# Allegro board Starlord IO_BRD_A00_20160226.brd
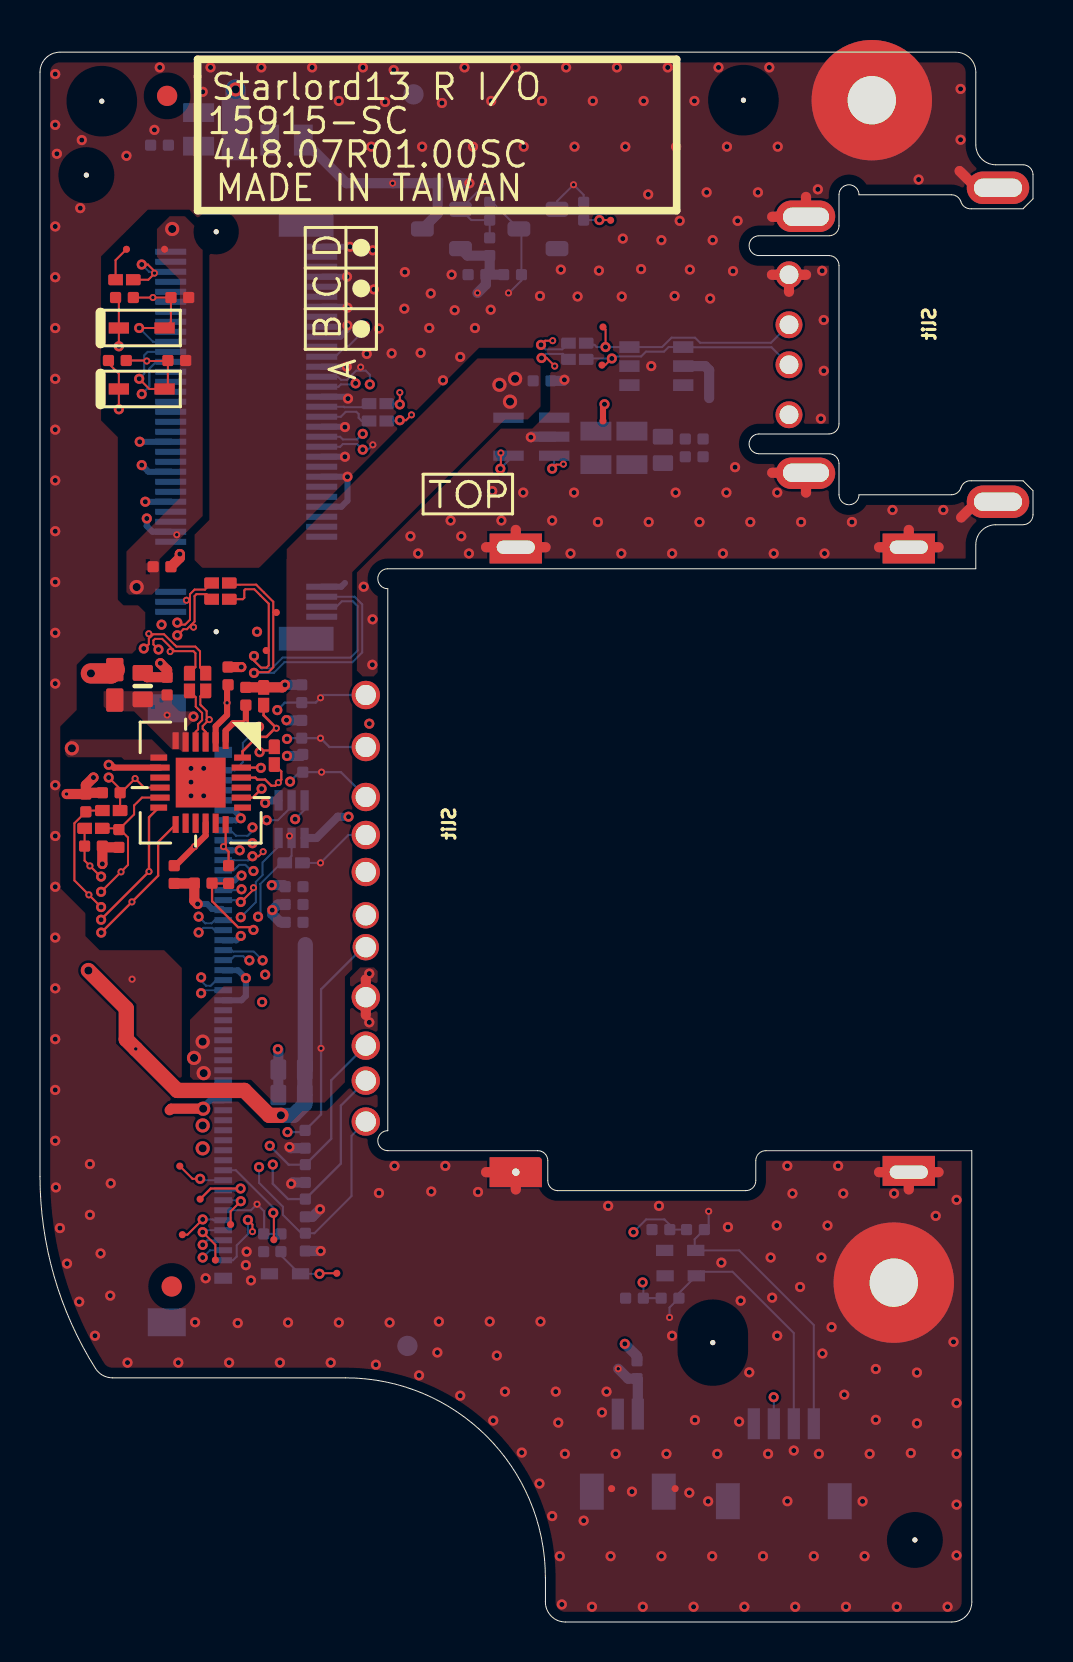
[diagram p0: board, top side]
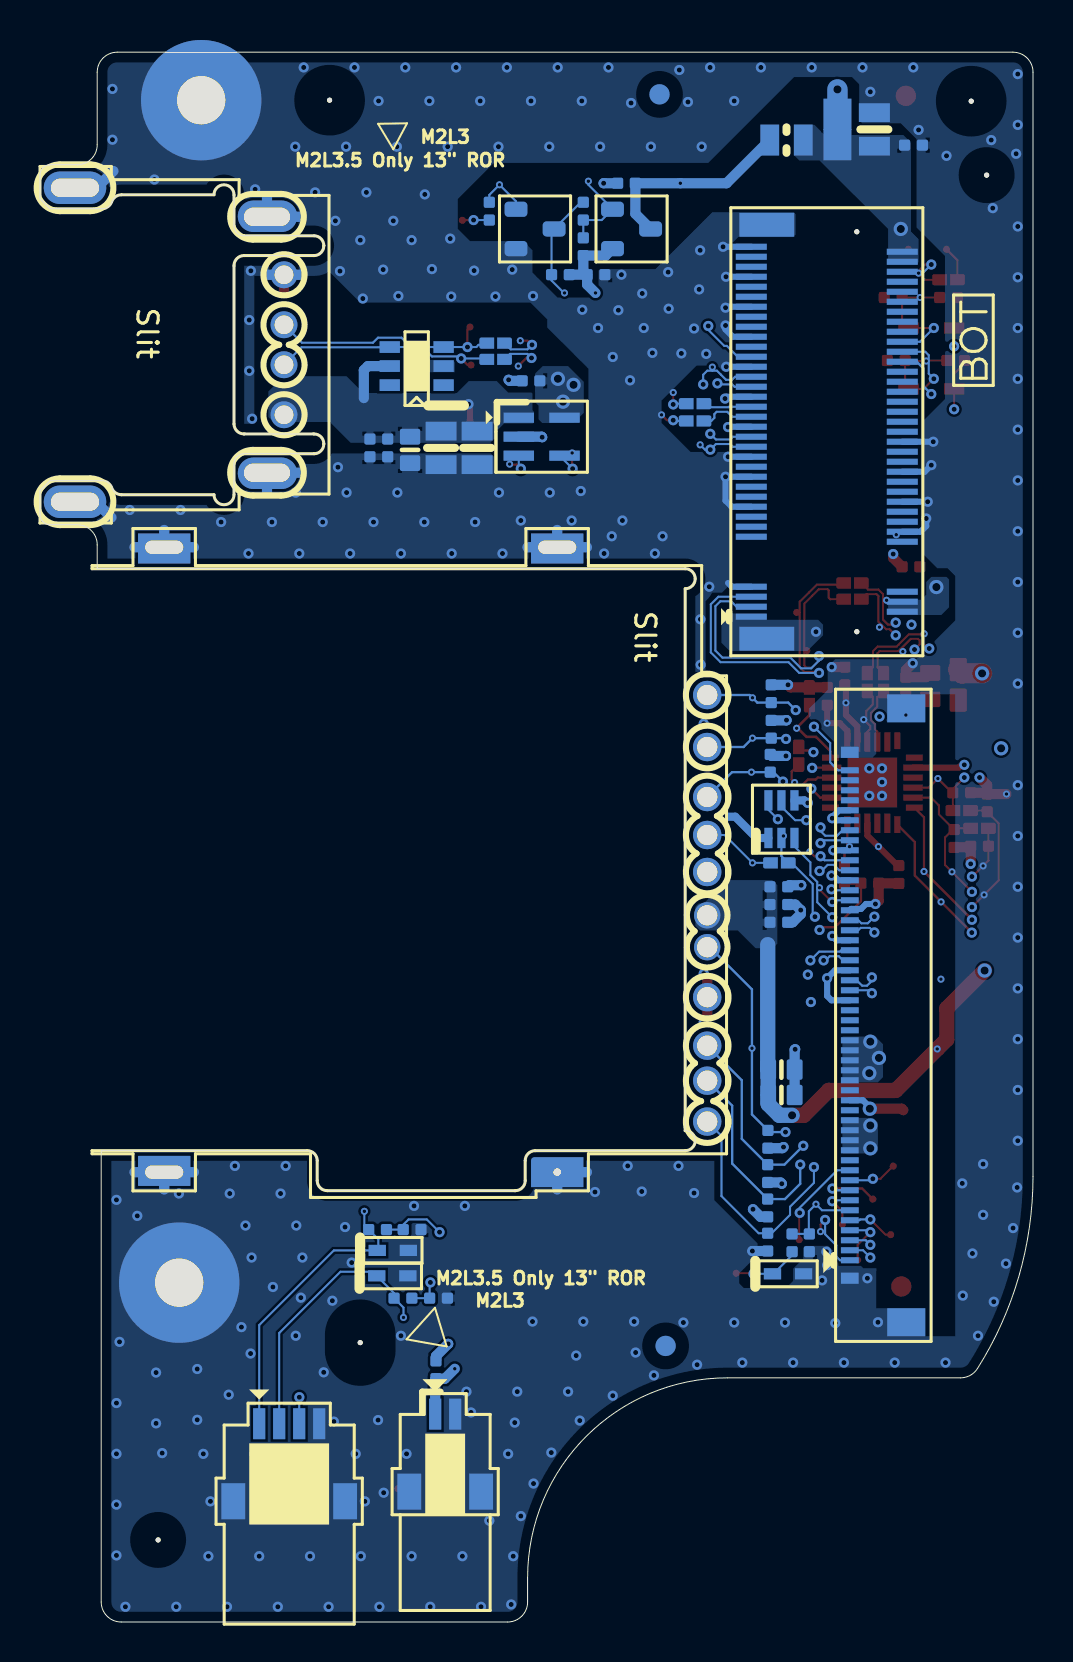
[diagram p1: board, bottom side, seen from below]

Outline 49.65 x 78.5 mm; copper layers: TOP, L2GND, L3, L4, L5VCC, L6, L7GND, BOTTOM. Coordinates in mm from the lower left corner of the outline.
Outline path: 0,77.5 0,22.28 arc(0.71,17.28) 2.78,12.68 arc(3.14,12.33) 3.62,12.21 15.27,12.21 arc(22.34,9.28) 25.27,2.21 25.27,1 arc(25.56,0.29) 26.27,0 45.59,0 arc(46.3,0.29) 46.59,1 46.59,23.57 36.29,23.57 arc(35.94,23.42) 35.79,23.07 35.79,22.07 arc(35.64,21.72) 35.29,21.57 25.89,21.57 arc(25.54,21.72) 25.39,22.07 25.39,23.07 arc(25.24,23.42) 24.89,23.57 17.39,23.57 arc(16.89,24.07) 17.39,24.57 17.39,51.67 arc(16.89,52.17) 17.39,52.67 46.79,52.67 46.79,53.87 arc(47.08,54.58) 47.79,54.87 49.15,54.87 arc(49.5,55.02) 49.65,55.37 49.65,56.57 49.15,57.07 46.57,57.07 arc(46.25,56.99) 46.05,56.72 arc(45.87,56.47) 45.57,56.37 40.95,56.37 arc(40.45,55.87) 39.95,56.37 39.95,57.92 arc(39.8,58.27) 39.45,58.42 35.95,58.42 arc(35.46,58.92) 35.95,59.41 39.45,59.41 arc(39.8,59.56) 39.95,59.91 39.95,67.83 arc(39.8,68.18) 39.45,68.33 35.95,68.33 arc(35.46,68.83) 35.95,69.32 39.45,69.32 arc(39.8,69.47) 39.95,69.82 39.95,71.37 arc(40.45,71.87) 40.95,71.37 45.57,71.37 arc(45.87,71.27) 46.05,71.02 arc(46.25,70.75) 46.57,70.67 49.15,70.67 49.65,71.17 49.65,72.37 arc(49.5,72.72) 49.15,72.87 47.79,72.87 arc(47.08,73.16) 46.79,73.87 46.79,77.5 arc(46.5,78.21) 45.79,78.5 1,78.5 arc(0.29,78.21) 0,77.5

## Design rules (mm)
constraint set DEFAULT: min track width 0.127, pair gap 0.102
net group POWER_20: nets +RTC_VCC RTC_VCC_C
net group POWER_60: nets 3D3V_S5 WLANPWR
net group CARD_CLK: nets 12MHZ_IN
net group CPU_SIDE: nets PLT_RST#
net group OTHER_4: nets AUX_EN_WOWL AUX_EN_WOWL_R BLUETOOTH_EN BLUETOOTH_EN_R CLKREQ_PCIE#1 JIO3_PCIE_WAKE# JIO3_PCIE_WAKE#_R KBC_PWRBTN# KBC_PWRBTN#_C LOOP SD_CD# SD_CD#_C SD_CD#_CARD SD_WP#/MS_DATA1 SD_WP#/MS_DATA1_C USB_OC1# USB_PWR_EN# VOL_DOWN# VOL_DOWN#_R VOL_UP# VOL_UP#_R WIFI_RF_EN WIFI_RF_EN_R WLAN_EN# WLAN_EN_R#
net group POWER_12: nets CARD_AV18 CARD_RREF SDREG
net group SD_MMC_SIG-MWS: nets SD_MMC_CLK/MS_DATA2 SD_MMC_CMM/MS_DATA3 SD_MMC_DAT1 SD_MMC_DATA0/MS_DATA5 SD_MMC_DATA2/MS_BS SD_MMC_DATA3/MS_CLK SD_MMC_DATA3/MS_CLK_R SP5

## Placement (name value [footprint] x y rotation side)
AFTP710  AFTE14P-GP  [AFTE14P-75]  31.76 6.67 0 top
AFTP716  AFTE14P-GP  [AFTE14P-75]  14.84 17.44 0 top
AFTP717  AFTE14P-GP  [AFTE14P-75]  11.69 19.12 0 top
AFTP718  AFTE14P-GP  [AFTE14P-75]  6.99 22.8 0 top
AFTP2507  AFTE14P-GP  [AFTE14P-75]  28.58 6.67 0 top
AFTP2508  AFTE14P-GP  [AFTE14P-75]  6.48 25.59 0 top
AFTP3404  DO NOT STUFF  [AFTE14P-75]  28.1 62.85 0 top
AFTP3405  DO NOT STUFF  [AFTE14P-75]  28.15 64.76 0 top
AFTP3406  DO NOT STUFF  [AFTE14P-75]  28.15 60.06 0 top
AFTP6108  DO NOT STUFF  [AFTE14P-75]  8.01 21.15 0 top
AFTP6109  DO NOT STUFF  [AFTE14P-75]  9.53 19.88 0 top
AFTP6110  DO NOT STUFF  [AFTE14P-75]  7.12 19.37 0 top
AFTP6111  DO NOT STUFF  [AFTE14P-75]  11.82 50.48 0 top
AFTP6112  DO NOT STUFF  [AFTE14P-75]  8.77 18.1 0 top
AFTP6113  DO NOT STUFF  [AFTE14P-75]  6.23 68.65 0 top
AFTP6114  DO NOT STUFF  [AFTE14P-75]  11.31 48.58 0 top
AFTP6115  DO NOT STUFF  [AFTE14P-75]  4.32 68.65 0 top
AFTP6117  DO NOT STUFF  [AFTE14P-75]  28.53 70.09 0 top
C311  SCD1U10V2KX-5GP  [C402H22]  12.71 35.88 90 bottom
C312  SCD01U16V2KX-3GP  [C402H22]  12.71 36.77 90 bottom
C313  SC4D7U6D3V3KX-GP  [C603H36]  12.58 27.62 90 bottom
C314  SC10U6D3V3KX-GP  [C603H38]  12.58 26.35 90 bottom
C315  DO NOT STUFF  [C402H22]  8.16 36.95 270 top
C316  SCD1U10V2KX-5GP  [C402H22]  6.36 46.8 180 top
C317  SC4D7U6D3V3KX-GP  [C603H36]  5.14 46.8 180 top
C318  SC1U6D3V2KX-GP  [C402H22]  10.29 46.29 180 top
C319  SC1U6D3V2KX-GP  [C402H22]  6.71 37.38 0 top
C320  SCD1U10V2KX-5GP  [C402H22]  12.71 34.99 90 bottom
C413  SC22U6D3V5MX-2GP  [C805H58]  27.79 58.71 180 bottom
C414  SC22U6D3V5MX-2GP  [C805H58]  29.6 58.71 180 bottom
C429  SCD1U16V2KX-3GP  [C402H22]  25.1 62.07 270 bottom
C431  SCD1U16V2KX-3GP  [C402H22]  33.15 58.71 180 bottom
C432  SC1U25V3KX-1-GP  [C603H36]  31.15 58.61 180 bottom
C507  DO NOT STUFF  [C402H22]  22.49 68.77 0 bottom
C508  DO NOT STUFF  [C402H22]  20.33 71.95 270 bottom
C509  DO NOT STUFF  [C402H22]  21.85 67.38 90 bottom
C510  SCD1U16V2KX-3GP  [C402H22]  5.98 73.85 90 bottom
C511  SCD1U16V2KX-3GP  [C402H22]  6.1 52.77 90 top
C512  SC10U6D3V5KX-1GP  [C805H54]  7.93 74.64 0 bottom
CARD34  RTS5176E-GRT-GP  [QFN24-G2D5H40-U]  8.03 41.98 0 top
D503  RB751V-40H-GP  [SOD323AKH38]  5.09 61.66 270 top
D504  RB751V-40H-GP  [SOD323AKH38]  5.09 64.71 270 top
EC308  SC6D8P50V2DN-GP  [C402H22]  13.27 22.42 180 bottom
EC309  SC6D8P50V2DN-GP  [C402H22]  13.27 19 180 bottom
EC310  SC6D8P50V2DN-GP  [C402H22]  13.27 20.71 180 bottom
EC311  SC6D8P50V2DN-GP  [C402H22]  13.25 24.14 180 bottom
EC312  SC6D8P50V2DN-GP  [C402H22]  13.09 46.42 0 bottom
EC313  SC6D8P50V2DN-GP  [C402H22]  13.14 42.94 0 bottom
EC314  SC6D8P50V2DN-GP  [C402H22]  13.09 44.64 0 bottom
EC609  SC1KP50V2KX-1GP  [C402H22]  31.04 19.62 270 bottom
EC610  SC1KP50V2KX-1GP  [C402H22]  29.72 16.19 270 bottom
EC611  SCD1U25V2KX-GP  [C402H22]  11.18 18.96 180 bottom
ED609  AZ5125-01H-R7G-GP  [SOD-523-4H28]  12.25 17.41 90 bottom
ED610  AZ5125-01H-R7G-GP  [SOD-523-4H28]  32.04 17.31 90 bottom
ED611  AZ5125-01H-R7G-GP  [SOD-523-4H28]  32.01 18.58 90 bottom
H11  HOLE237R95-GP  [HOLE237R95]  41.59 76.1 180 bottom
H12  HOLE237R95-GP  [HOLE237R95]  42.69 16.97 180 bottom
IOBD2  IPEX-CON50-1-GP  [20455-050E-76]  6.34 30.34 90 bottom
NOREF  -  [unnamed]  3.09 76.05 0 top
NOREF#2  -  [#2]  14.53 67.45 90 top
NOREF#3  -  [#2]  30.03 76.44 0 top
NOREF#4  -  [unnamed]  35.17 76.1 0 top
NOREF#5  *  [unnamed]  6.58 16.78 0 top
NOREF#6  -  [unnamed]  33.64 13.97 0 top
NOREF#7  -  [#2]  -117.09 -19.11 0 top
NOREF#8  -  [unnamed]  43.74 4.1 0 top
NOREF#9  -  [unnamed]  2.32 72.35 0 top
NOREF#10  *  [unnamed]  6.36 76.32 0 top
NOREF#11  -  [#2]  -115.31 -42.48 0 top
NOREF#12  *  [unnamed]  18.37 13.81 180 bottom
NOREF#13  -  [#2]  2.98 64.1 90 bottom
NOREF#14  *  [unnamed]  18.68 76.39 180 bottom
PWBD1  ACES-CON4-29-GP  [50224-0040N-001]  37.19 6.04 180 bottom
Q503  DO NOT STUFF  [SOT23DGS2D4H48]  20.07 69.66 270 bottom
Q504  DO NOT STUFF  [SOT23DGS2D4H44]  24.9 69.66 270 bottom
Q3302  2N7002KDW-GP  [SOT-363H44]  12.58 40.15 180 bottom
R313  10KR2J-3-GP  [R402H16]  3.56 41.47 90 top
R314  -  [0R0402-PAD]  2.67 39.69 270 top
R316  100KR2J-1-GP  [R402H16]  2.67 38.8 270 top
R317  10KR2J-3-GP  [R402H16]  3.94 39.18 180 top
R318  100KR2J-1-GP  [R402H16]  2.29 40.96 0 top
R319  -  [0R0402-PAD]  8.29 47 0 top
R320  -  [0R0402-PAD]  7.47 47 0 top
R321  -  [0R0402-PAD]  12.68 37.96 270 bottom
R322  -  [0R0603-PAD]  3.74 46.78 0 top
R323  -  [0R0402-PAD]  11.18 46.29 180 top
R324  33R2J-2-GP  [R402H16]  9.43 37.38 180 top
R325  -  [0R0402-PAD]  11.72 43.32 0 top
R326  6K2R2F-GP  [R402H16]  9.4 47.31 180 top
R422  DO NOT STUFF  [R402H16]  32.26 58.71 180 bottom
R501  10KR2J-3-GP  [R402H16]  6.99 66.23 270 top
R502  10KR2J-3-GP  [R402H16]  6.84 63.08 270 top
R510  -  [0R0402-PAD]  9.02 51.96 270 top
R511  -  [0R0402-PAD]  9.02 51.14 270 top
R512  -  [0R0805-PAD]  9.78 74.64 180 bottom
R514  DO NOT STUFF  [R805H24]  12.33 74.11 90 bottom
R516  DO NOT STUFF  [R402H16]  27.18 70.55 0 bottom
R517  DO NOT STUFF  [R402H16]  22.49 70.55 180 bottom
R519  DO NOT STUFF  [R402H16]  23.63 67.38 270 bottom
R520  0R2J-2-GP  [R402H16]  4.22 66.23 270 top
R521  0R2J-2-GP  [R402H16]  3.87 63.08 270 top
R522  -  [0R0402-PAD]  16.9 60.92 270 bottom
R523  -  [0R0402-PAD]  16.9 60.06 270 bottom
R524  -  [0R0402-PAD]  4.22 67.12 90 top
R601  1KR2J-1-GP  [R402H16]  29.85 12.61 180 bottom
R613  470R2J-2-GP  [R402H16]  12.05 18.96 180 bottom
R614  470R2J-2-GP  [R402H16]  32.77 19.62 270 bottom
R615  470R2J-2-GP  [R402H16]  31.5 16.19 270 bottom
R3314  -  [0R0402-PAD]  3.56 40.58 270 top
R4032  -  [0R0402-PAD]  26.87 63.95 270 bottom
R4033  -  [0R0402-PAD]  26.87 63.14 270 bottom
RTC1  ACES-CON2-20-GP-U  [50224-0020N-W02]  29.39 6.52 180 bottom
SD1  SDCARD-11P-17-GP  [PSDBR3-11GLBS1NN4H0]  43.44 38.12 270 bottom
U401  SY6288DAAC-GP  [SOT-23-5H56]  24.57 59.27 270 bottom
U402  AZC099-04S-1-GP  [SOT-6H58]  30.82 62.8 90 bottom
USB4  SKT-USB8-186-GP  [SKT-USB8-166140-2]  47.9 63.87 270 bottom
WLAN1  SKT-NGFF75P-64-GP  [DAN05-67306-050001]  8.81 59.52 270 bottom

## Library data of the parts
AFTP710 AFTP716-AFTP718 AFTP2507 AFTP2508 = AFTE14P-75: tolerance: ZZ.AFT14.101
AFTP3404-AFTP3406 AFTP6108-AFTP6115 AFTP6117 = AFTE14P-75
C311 C316 C320 = C402H22: tolerance: 78.10423.2FL
C312 = C402H22: tolerance: 78.10321.2FL
C313 C317 = C603H36: tolerance: 78.47520.5BL
C314 = C603H38: tolerance: 78.10620.5BL
C315 C507-C509 = C402H22
C318 C319 = C402H22: tolerance: 78.10520.5FL
C413 C414 = C805H58: tolerance: 78.22610.51L
C429 C431 C510 C511 = C402H22: tolerance: 78.10421.2FL
C432 = C603H36: tolerance: 78.10522.5BL
C512 = C805H54: tolerance: 78.10620.51L
CARD34 = QFN24-G2D5H40-U: tolerance: 71.05176.A03
D503 D504 = SOD323AKH38: tolerance: 83.R2004.G8F
EC308-EC314 = C402H22: tolerance: 78.6R864.1FL
EC609 EC610 = C402H22: tolerance: 78.10224.2FL
EC611 = C402H22: tolerance: 78.10422.5FL
ED609-ED611 = SOD-523-4H28: tolerance: 75.05125.070
H11 H12 = HOLE237R95: tolerance: ZZ.00PAD.921
IOBD2 = 20455-050E-76: tolerance: 020.F0574.0050
PWBD1 = 50224-0040N-001: tolerance: 20.F1639.004
Q503 = SOT23DGS2D4H48
Q504 = SOT23DGS2D4H44
Q3302 = SOT-363H44: tolerance: 84.2N702.A3F
R313 R317 R501 R502 = R402H16: tolerance: 63.10334.1DL
R314 R319-R321 R323 R325 R510 R511 R522-R524 R3314 R4032 R4033 = 0R0402-PAD: tolerance: ZZ.R0402.ZZZ
R316 R318 = R402H16: tolerance: 63.10434.1DL
R322 = 0R0603-PAD: tolerance: ZZ.R0603.ZZZ
R324 = R402H16: tolerance: 63.33034.1DL
R326 = R402H16: tolerance: 64.62015.6DL
R422 R516 R517 R519 = R402H16
R512 = 0R0805-PAD: tolerance: ZZ.R0805.ZZZ
R514 = R805H24
R520 R521 = R402H16: tolerance: 63.R0034.1DL
R601 = R402H16: tolerance: 63.10234.1DL
R613-R615 = R402H16: tolerance: 63.47134.1DL
RTC1 = 50224-0020N-W02: tolerance: 20.F1639.002
SD1 = PSDBR3-11GLBS1NN4H0: tolerance: 062.10002.0301
U401 = SOT-23-5H56: tolerance: 074.06288.009B
U402 = SOT-6H58: tolerance: 75.09904.07C
USB4 = SKT-USB8-166140-2: tolerance: 022.10005.0861
WLAN1 = DAN05-67306-050001: tolerance: 062.10003.0251

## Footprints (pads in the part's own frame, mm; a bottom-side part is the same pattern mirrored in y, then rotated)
0R0402-PAD
  custom 0.14x0.14 smd: 1(0,0.445) 2(0,-0.445)
0R0603-PAD
  custom 0.216x0.216 smd: 1(0,0.851) 2(0,-0.673)
0R0805-PAD
  rect 1.397x1.562 smd: 1(0,0.965)
  rect 1.397x1.569 smd: 2(0,-0.965)
20455-050E-76
  rect 0.305x0.889 smd: 1(-12.25,2.82) 2(-11.75,2.82) 3(-11.25,2.82) 4(-10.75,2.82) 5(-10.25,2.82) 6(-9.75,2.82) 7(-9.25,2.82) 8(-8.75,2.82) 9(-8.25,2.82) 10(-7.75,2.82) 11(-7.25,2.82) 12(-6.75,2.82) 13(-6.25,2.82) 14(-5.75,2.82) 15(-5.25,2.82) 16(-4.75,2.82) 17(-4.25,2.82) 18(-3.75,2.82) 19(-3.25,2.82) 20(-2.75,2.82) 21(-2.25,2.82) 22(-1.75,2.82) 23(-1.25,2.82) 24(-0.75,2.82) 25(-0.25,2.82) 26(0.25,2.82) 27(0.75,2.82) 28(1.25,2.82) 29(1.75,2.82) 30(2.25,2.82) 31(2.75,2.82) 32(3.25,2.82) 33(3.75,2.82) 34(4.25,2.82) 35(4.75,2.82) 36(5.25,2.82) 37(5.75,2.82) 38(6.25,2.82) 39(6.75,2.82) 40(7.25,2.82) 41(7.75,2.82) 42(8.25,2.82) 43(8.75,2.82) 44(9.25,2.82) 45(9.75,2.82) 46(10.25,2.82) 47(10.75,2.82) 48(11.25,2.82) 49(11.75,2.82) 50(12.25,2.82)
  rect 1.397x1.905 smd: 51(-15.35,0) 52(15.35,0)
  rect 0.559x0.889 smd: 53(-13.15,2.82) 54(13.15,2.82)
50224-0020N-W02
  rect 0.61x1.549 smd: 1(-0.5,3.876) 2(0.5,3.876)
  rect 1.194x1.803 smd: 3(-1.797,0) 4(1.797,0)
50224-0040N-001
  rect 0.61x1.549 smd: 1(-1.5,3.875) 2(-0.5,3.875) 3(0.5,3.875) 4(1.5,3.875)
  rect 1.194x1.803 smd: 5(-2.797,0) 6(2.797,0)
AFTE14P-75
  round 0.356 smd: 1(0,0)
C402H22
  custom 0.14x0.14 smd: 1(0,0.445) 2(0,-0.445)
C603H36
  custom 0.197x0.197 smd: 1(0,0.66) 2(0,-0.66)
C603H38
  custom 0.197x0.197 smd: 1(0,0.66) 2(0,-0.66)
C805H54
  rect 1.549x0.94 smd: 1(0,0.838) 2(0,-0.838)
C805H58
  rect 1.549x0.94 smd: 1(0,0.838) 2(0,-0.838)
DAN05-67306-050001
  round 0.254 hole 1.651 unplated: (-10,0)
  round 0.254 hole 1.168 unplated: (10,0)
  rect 0.305x1.549 smd: 1(9.25,-5.275) 2(9,2.275) 3(8.75,-5.275) 4(8.5,2.275) 5(8.25,-5.275) 6(8,2.275) 7(7.75,-5.275) 16(5.5,2.275) 17(5.25,-5.275) 18(5,2.275) 19(4.75,-5.275) 20(4.5,2.275) 21(4.25,-5.275) 22(4,2.275) 23(3.75,-5.275) 24(3.5,2.275) 25(3.25,-5.275) 26(3,2.275) 27(2.75,-5.275) 28(2.5,2.275) 29(2.25,-5.275) 30(2,2.275) 31(1.75,-5.275) 32(1.5,2.275) 33(1.25,-5.275) 34(1,2.275) 35(0.75,-5.275) 36(0.5,2.275) 37(0.25,-5.275) 38(0,2.275) 39(-0.25,-5.275) 40(-0.5,2.275) 41(-0.75,-5.275) 42(-1,2.275) 43(-1.25,-5.275) 44(-1.5,2.275) 45(-1.75,-5.275) 46(-2,2.275) 47(-2.25,-5.275) 48(-2.5,2.275) 49(-2.75,-5.275) 50(-3,2.275) 51(-3.25,-5.275) 52(-3.5,2.275) 53(-3.75,-5.275) 54(-4,2.275) 55(-4.25,-5.275) 56(-4.5,2.275) 57(-4.75,-5.275) 58(-5,2.275) 59(-5.25,-5.275) 60(-5.5,2.275) 61(-5.75,-5.275) 62(-6,2.275) 63(-6.25,-5.275) 64(-6.5,2.275) 65(-6.75,-5.275) 66(-7,2.275) 67(-7.25,-5.275) 68(-7.5,2.275) 69(-7.75,-5.275) 70(-8,2.275) 71(-8.25,-5.275) 72(-8.5,2.275) 73(-8.75,-5.275) 74(-9,2.275) 75(-9.25,-5.275)
  rect 1.194x2.743 smd: 76(10.35,-4.5) 77(-10.35,-4.5)
HOLE237R95
  round 6.02 hole 2.413: 1(0,0)
PSDBR3-11GLBS1NN4H0
  round 1.422 hole 1.016: 1(-8.235,27.15) 2(-5.635,27.15) 3(-3.135,27.15) 4(-1.235,27.15) 5(0.615,27.15) 8(6.875,27.15) 9(9.3,27.15) 10(11.05,27.15) 11(13.095,27.15)
  round 1.321 hole 1.016: 6(2.78,27.15) 7(4.375,27.15)
  custom 0.375x0.375 hole 0.66x1.905: 12(15.625,19.65)
  rect 1.499x2.616 hole 0.66x1.905: 13(-15.625,19.65) 14(15.625,0) 15(-15.625,0)
QFN24-G2D5H40-U
  rect 0.305x0.838 smd: 1(1.25,2.095) 6(-1.25,2.095) 13(-1.25,-2.095) 18(1.25,-2.095)
  rect 0.305x0.965 smd: 2(0.751,2.032) 3(0.25,2.032) 4(-0.25,2.032) 5(-0.751,2.032) 14(-0.751,-2.032) 15(-0.25,-2.032) 16(0.25,-2.032) 17(0.751,-2.032)
  rect 0.838x0.305 smd: 7(-2.095,1.25) 12(-2.095,-1.25) 19(2.095,-1.25) 24(2.095,1.25)
  rect 0.965x0.305 smd: 8(-2.032,0.751) 9(-2.032,0.25) 10(-2.032,-0.25) 11(-2.032,-0.751) 20(2.032,-0.751) 21(2.032,-0.25) 22(2.032,0.25) 23(2.032,0.751)
  rect 2.489x2.489 smd: 25(0,0)
R402H16
  custom 0.14x0.14 smd: 1(0,0.445) 2(0,-0.445)
R805H24
  rect 1.549x0.94 smd: 1(0,0.838) 2(0,-0.838)
SKT-USB8-166140-2
  round 1.346 hole 0.94: 1(3.5,10.45) 2(1,10.45) 3(-1,10.45) 4(-3.5,10.45)
  oval 1.575x2.972 hole 0.914x2.311: 5(-6.4,9.6) 6(6.4,9.6)
  oval 1.626x3.124 hole 0.914x2.413: 7(-7.85,0) 8(7.85,0)
SOD323AKH38
  rect 0.559x1.016 smd: A(0,1.143) K(0,-1.143)
SOD-523-4H28
  rect 0.559x0.864 smd: 1(0,0.778) 2(0,-0.778)
SOT23DGS2D4H44
  custom 0.191x0.191 smd: D(0,0.953) G(-0.984,-0.953) S(0.984,-0.953)
SOT23DGS2D4H48
  custom 0.191x0.191 smd: D(0,0.953) G(-0.984,-0.953) S(0.984,-0.953)
SOT-6H58
  rect 0.584x1.016 smd: 1(-0.953,-1.346) 2(0,-1.346) 3(0.953,-1.346) 4(0.953,1.346) 5(0,1.346) 6(-0.953,1.346)
SOT-23-5H56
  rect 0.508x1.524 smd: 1(-0.95,-1.143) 2(0,-1.143) 3(0.95,-1.143) 4(0.95,1.143) 5(-0.95,1.143)
SOT-363H44
  rect 0.406x1.016 smd: 1(-0.65,-0.94) 2(0,-0.94) 3(0.65,-0.94) 4(0.65,0.94) 5(0,0.94) 6(-0.65,0.94)
unnamed
  round 0.254 hole 2.921 unplated: (0,0)

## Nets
5V_S5: C429.1 IOBD2.19 IOBD2.20 IOBD2.21 IOBD2.22 IOBD2.23 U401.5
GND: AFTP710.1 AFTP2507.1 C311.2 C312.2 C313.2 C314.2 C315.2 C316.2 C317.2 C318.2 C319.2 C320.2 C413.2 C414.2 C429.2 C431.2 C432.2 C508.2 C509.2 C510.2 C511.2 C512.2 CARD34.25 EC308.2 EC309.2 EC310.2 EC311.2 EC312.2 EC313.2 EC314.2 EC609.1 EC610.1 EC611.2 ED609.2 ED610.2 ED611.2 H11.1 H12.1 IOBD2.27 IOBD2.30 IOBD2.33 IOBD2.36 IOBD2.39 IOBD2.42 IOBD2.45 IOBD2.46 IOBD2.51 IOBD2.52 IOBD2.53 IOBD2.54 PWBD1.4 PWBD1.5 PWBD1.6 Q504.S Q3302.1 Q3302.4 R323.2 R326.2 R422.2 RTC1.2 RTC1.3 RTC1.4 SD1.5 SD1.8 SD1.12 SD1.13 SD1.14 SD1.15 U401.2 U402.2 USB4.4 USB4.5 USB4.6 USB4.7 USB4.8 WLAN1.1 WLAN1.7 WLAN1.18 WLAN1.23 WLAN1.24 WLAN1.29 WLAN1.30 WLAN1.33 WLAN1.36 WLAN1.39 WLAN1.45 WLAN1.51 WLAN1.57 WLAN1.63 WLAN1.69 WLAN1.75 WLAN1.76 WLAN1.77
3D3V_CARD: C311.1 C312.1 C313.1 C314.1 C320.1 CARD34.7 SD1.6
3D3V_CARD_S0: C316.1 C317.1 CARD34.5 CARD34.6 CARD34.8 R322.2
3D3V_S0: IOBD2.12 IOBD2.13 IOBD2.14 IOBD2.15 R313.1 R316.1 R317.1 R318.1 R322.1 R512.1
3D3V_S5: C507.1 C509.1 Q503.S R519.1
3D3V_WLAN_S0: AFTP6113.1 C510.1 C511.1 C512.1 R501.1 R502.1 R512.2 R514.2 WLAN1.2 WLAN1.4 WLAN1.72 WLAN1.74
12MHZ_IN: CARD34.24 R323.1
+RTC_VCC: AFTP2508.1 IOBD2.17 R601.1
AUX_EN_WOWL: AFTP6117.1 R516.1
AUX_EN_WOWL_R: Q504.G R516.2
BLUETOOTH_EN: AFTP6112.1 D503.K IOBD2.4 R521.2
BLUETOOTH_EN_R: D503.A R502.2 R521.1 WLAN1.54
CARD_AV18: C318.1 CARD34.1
CARD_RREF: CARD34.2 R326.1
CLKREQ_PCIE#1: AFTP6109.1 IOBD2.7 WLAN1.53
JIO3_PCIE_WAKE#: AFTP6115.1 R524.1
JIO3_PCIE_WAKE#_R: R524.2 WLAN1.70
KBC_PWRBTN#: EC611.1 IOBD2.6 R613.1
KBC_PWRBTN#_C: AFTP716.1 ED609.1 PWBD1.3 R613.2
LOOP: IOBD2.1 IOBD2.50
PCIE_RX_CPU_N5: IOBD2.43 R522.2
PCIE_RX_CPU_P5: IOBD2.44 R523.2
PCIE_TX_WLAN_N5: IOBD2.41 WLAN1.37
PCIE_TX_WLAN_P5: IOBD2.40 WLAN1.35
PEG_CLK1_CPU: IOBD2.37 WLAN1.47
PEG_CLK1_CPU#: IOBD2.38 WLAN1.49
PLT_RST#: AFTP6108.1 IOBD2.8 WLAN1.52
RTC_VCC_C: R601.2 RTC1.1
SD_CD#: Q3302.2 R318.2 R321.1 R3314.2
SD_CD#_C: R321.2 SD1.4
SD_CD#_CARD: CARD34.10 Q3302.6 R313.2 R3314.1
SD_MMC_CLK/MS_DATA2: C315.1 EC311.1 R324.1 SD1.7
SD_MMC_CMM/MS_DATA3: CARD34.20 EC313.1 SD1.3
SD_MMC_DAT1: CARD34.12 EC310.1 SD1.10
SD_MMC_DATA0/MS_DATA5: CARD34.13 EC308.1 SD1.9
SD_MMC_DATA2/MS_BS: CARD34.23 EC312.1 SD1.1
SD_MMC_DATA3/MS_CLK: EC314.1 R325.1 SD1.2
SD_MMC_DATA3/MS_CLK_R: CARD34.22 R325.2
SD_WP#/MS_DATA1: EC309.1 Q3302.5 R314.2 R316.2 SD1.11
SD_WP#/MS_DATA1_C: CARD34.11 Q3302.3 R314.1 R317.2
SDREG: C319.1 CARD34.16
SP5: CARD34.18 R324.2
USB20_VCCC: AFTP3406.1 C413.1 C414.1 C431.1 C432.1 R422.1 U401.1 U402.5 USB4.1
USB_CPU_PN2_C: IOBD2.32 R4033.1
USB_CPU_PN5_C: IOBD2.35 R510.2
USB_CPU_PN7_C: IOBD2.29 R319.1
USB_CPU_PP2_C: IOBD2.31 R4032.1
USB_CPU_PP5_C: IOBD2.34 R511.2
USB_CPU_PP7_C: IOBD2.28 R320.1
USB_DN7_R: CARD34.3 R319.2
USB_DP7_R: CARD34.4 R320.2
USB_OC1#: IOBD2.3 U401.3
USB_PN2_R: AFTP3404.1 R4033.2 U402.4 USB4.2
USB_PN5_R: AFTP6111.1 R510.1 WLAN1.5
USB_PP2_R: AFTP3405.1 R4032.2 U402.3 USB4.3
USB_PP5_R: AFTP6114.1 R511.1 WLAN1.3
USB_PWR_EN#: IOBD2.2 U401.4
VOL_DOWN#: AFTP718.1 EC609.2 IOBD2.9 R614.1
VOL_DOWN#_R: ED611.1 PWBD1.1 R614.2
VOL_UP#: AFTP717.1 EC610.2 IOBD2.10 R615.1
VOL_UP#_R: ED610.1 PWBD1.2 R615.2
WIFI_RF_EN: AFTP6110.1 D504.K IOBD2.5 R520.2
WIFI_RF_EN_R: D504.A R501.2 R520.1 WLAN1.56
WLAN_EN#: Q504.D R517.1 R519.2
WLAN_EN_R#: C507.2 Q503.G R517.2
WLANPWR: C508.1 Q503.D R514.1
WLANTX_N3: R522.1 WLAN1.43
WLANTX_P3: R523.1 WLAN1.41

Pads without a net: CARD34 9 14 15 17 19 21; IOBD2 11 16 18 24 25 26 47 48 49; U402 1 6; WLAN1 6 16 17 19 20 21 22 25 26 27 28 31 32 34 38 40 42 44 46 48 50 55 58 59 60 61 62 64 65 66 67 68 71 73

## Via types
v1: diameter 0.508, hole 0.254, TOP to BOTTOM, 370 vias
v2: diameter 0.356, hole 0.178, TOP to BOTTOM, 51 vias
v3: diameter 0.711, hole 0.406, TOP to BOTTOM, 16 vias

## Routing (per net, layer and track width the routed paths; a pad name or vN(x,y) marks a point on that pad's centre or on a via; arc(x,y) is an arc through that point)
5V_S5:
  vias: v2(12.48,39.31) v3(7.7,28.21) v3(8.13,29.02) v3(8.18,27.45) v3(22.97,61.87) v3(23.5,61.03) v3(23.76,62.17)
GND: length 198.6
  TOP w0.508: 37.45,66.52 USB4.4 ; USB4.4 38.3,67.37 ; USB4.4 36.6,67.37 ; 22.3,53.75 SD1.13 ; SD1.13 25.28,53.75 ; SD1.13 23.79,54.61 ; v1(12.25,46.86) 12.12,46.74 R323.2 C318.2 ; 45.98,72.56 46.82,71.72 USB4.7 ; 41.95,22.5 SD1.14 ; SD1.14 43.44,21.63 ; SD1.14 44.93,22.5 ; C319.2 7.7,36.93 C315.2 7.71,36.07 v1(7.88,35.91) ; 22.3,22.5 SD1.12 23.79,21.63 ; 38.3,71.26 USB4.5 36.61,70.27 ; 36.61,57.47 USB4.6 38.3,56.48 ; R326.2 v1(10.06,47.75) ; 16.29,30.36 SD1.8 16.29,32.13 ; v1(6.99,53.41) 6.99,53.21 C511.2 ; SD1.15 43.44,54.61 ; SD1.15 44.93,53.75 ; SD1.15 41.95,53.75 ; USB4.8 46.84,56.02 46.06,55.23 ; v1(6.02,47.94) 6.36,47.6 C316.2 5.35,47.25 C317.2
  L3 w0.508: 16.29,30.36 SD1.8 ; SD1.8 16.29,32.13 ; SD1.8 15.4,31.25 ; 15.4,37.51 SD1.5 16.29,36.62 ; 22.3,22.5 SD1.12 23.79,21.63 ; 38.3,56.48 USB4.6 36.61,57.47 ; 37.45,66.52 USB4.4 ; USB4.4 38.3,67.37 ; USB4.4 36.6,67.37 ; 45.98,72.56 46.82,71.72 USB4.7 ; 22.3,53.75 SD1.13 ; SD1.13 25.28,53.75 ; SD1.13 23.79,54.61 ; 41.95,53.75 SD1.15 ; SD1.15 44.93,53.75 ; SD1.15 43.44,54.61 ; 36.61,70.27 USB4.5 38.3,71.26 ; 41.95,22.5 SD1.14 ; SD1.14 44.93,22.5 ; SD1.14 43.44,21.63
  L4 w0.508: 15.4,37.51 SD1.5 16.29,36.62 ; SD1.15 43.44,54.61 ; SD1.15 41.95,53.75 ; SD1.15 44.93,53.75 ; 22.3,22.5 SD1.12 23.79,21.63 ; 45.98,72.56 46.82,71.72 USB4.7 ; SD1.14 44.93,22.5 ; SD1.14 41.95,22.5 ; SD1.14 43.44,21.63 ; 38.3,56.48 USB4.6 36.61,57.47 ; 22.3,53.75 SD1.13 ; SD1.13 23.79,54.61 ; SD1.13 25.28,53.75 ; USB4.8 46.84,56.02 46.03,55.21 ; 37.45,66.52 USB4.4 ; USB4.4 38.3,67.37 ; USB4.4 36.6,67.37 ; 15.4,31.25 SD1.8 ; SD1.8 16.29,32.13 ; SD1.8 16.29,30.36 ; 36.61,70.27 USB4.5 38.3,71.26
  L6 w0.508: SD1.13 25.28,53.75 ; SD1.13 23.79,54.61 ; SD1.13 22.3,53.75 ; SD1.8 16.29,32.13 ; SD1.8 15.4,31.25 ; SD1.8 16.29,30.36 ; USB4.7 46.82,71.72 45.98,72.56 ; 36.61,57.47 USB4.6 38.3,56.48 ; 15.4,37.51 SD1.5 16.29,36.62 ; 43.44,21.63 SD1.14 ; SD1.14 41.95,22.5 ; SD1.14 44.93,22.5 ; 22.3,22.5 SD1.12 23.79,21.63 ; 41.95,53.75 SD1.15 ; SD1.15 43.44,54.61 ; SD1.15 44.93,53.75 ; USB4.4 38.3,67.37 ; USB4.4 37.45,66.52 ; USB4.4 36.6,67.37 ; 46.08,55.26 46.84,56.02 USB4.8 ; 36.61,70.27 USB4.5 38.3,71.26
  BOTTOM w0.305: v1(10.08,37.33) 9.97,37.33 9.73,37.09 IOBD2.39 ; v1(5.09,57.85) 5.42,57.52 WLAN1.30 ; IOBD2.36 9.09,35.66 8.6,35.66 8.35,35.91 v1(7.88,35.91) ; WLAN1.24 v1(5.27,56.02) ; IOBD2.33 9.82,34.09 v1(10.04,34.31) ; v1(5.34,55.18) 5.34,54.8 5.62,54.52 WLAN1.18 ; WLAN1.33 v1(15.25,58.27) ; IOBD2.45 9.81,40.09 9.91,40.19 v1(10.04,40.19) 10.04,40.25 9.7,40.59 IOBD2.46 ; WLAN1.7 15.06,51.77 15.25,51.96 ; IOBD2.42 v1(9.99,38.59) ; WLAN1.69 v1(15.35,67.27) ; v1(15.37,64.84) 15.37,64.63 15.01,64.27 WLAN1.57 ; WLAN1.45 15.31,61.27 v1(15.4,61.18) ; WLAN1.23 15.07,55.77 15.37,56.07 v1(15.37,57.27) WLAN1.29 ; WLAN1.63 15.33,65.77 v1(15.37,65.72) ; v1(15.25,59.76) 15.23,59.77 WLAN1.39 ; WLAN1.36 v1(4.99,59.02) ; IOBD2.30 9.9,32.59 v1(10.29,32.2) 10.29,31.31 10.08,31.09 IOBD2.27 ; WLAN1.51 v1(15.34,62.77) ; WLAN1.75 v1(15.5,68.77)
  BOTTOM w0.406: v1(11.26,40.96) 11.31,40.96 11.44,41.09 Q3302.4 ; Q3302.1 13.82,39.21 14.89,40.27 v1(15.43,40.27)
  BOTTOM w0.508: 36.61,57.47 USB4.6 38.3,56.48 ; EC313.2 13.06,43.31 v1(12.35,43.31) ; 38.3,67.37 USB4.4 36.6,67.37 ; v1(12.47,23.75) 12.53,23.69 EC311.2 ; EC308.2 12.62,21.98 v1(12.56,21.92) ; 22.3,53.75 SD1.13 ; SD1.13 25.28,53.75 ; SD1.13 23.79,54.61 ; 46.08,55.23 46.87,56.02 USB4.8 ; 38.3,71.26 USB4.5 36.61,70.27 ; C314.2 C313.2 11.92,28.61 v1(11.89,28.64) ; USB4.7 46.82,71.72 45.98,72.56 ; C508.2 v1(21.47,71.95) ; SD1.15 43.44,54.61 ; SD1.15 41.95,53.75 ; SD1.15 44.93,53.75 ; v1(11.59,36.84) 12.19,36.84 C312.2 ; 41.95,22.5 SD1.14 ; SD1.14 44.93,22.5 ; SD1.14 43.44,21.63 ; EC309.2 v1(14.03,18.55) ; 22.3,22.5 SD1.12 23.79,21.63 ; v1(24.54,59.25) 24.57,59.27 U401.2 ; C429.2 26.17,62.07 v1(26.22,62.12) ; v1(14,20.64) 13.62,20.26 EC310.2 ; v1(12.33,45.1) 12.34,45.09 EC314.2 ; C311.2 11.89,35.88 v1(11.61,35.6) 11.61,35.4 12.02,34.99 C320.2 ; EC312.2 v1(12.25,46.86)
  vias: v1(0.76,77.41) v1(0.76,74.87) v1(0.76,69.79) v1(0.76,67.25) v1(0.76,64.71) v1(0.76,62.17) v1(0.76,59.63) v1(0.76,57.09) v1(0.76,54.55) v1(0.76,52.01) v1(0.76,49.47) v1(0.76,46.93) v1(0.76,41.85) v1(0.76,39.31) v1(0.76,36.77) v1(0.76,34.23) v1(0.76,31.69) v1(0.76,29.15) v1(0.76,26.61) v1(0.76,24.07) v1(0.79,21.73) v1(0.84,73.42) v1(1,19.7) v1(1.35,17.92) v1(2.01,70.7) v1(1.96,16.02) v1(2.09,74.11) v1(2.5,22.9) v1(2.5,20.36) v1(2.75,14.31) v1(3.03,18.43) v1(3.54,21.93) v1(3.51,16.32) v1(4.32,73.32) v1(4.38,12.97) v1(5.72,74.61) v1(5.99,77.74) v1(6.08,49.87) v1(6.92,12.97) v1(7.55,42.69) v1(7.55,42) v1(7.55,41.31) v1(7.75,14.99) v1(8.13,76.52) v1(8.18,42.69) v1(8.18,41.31) v1(8.28,17.19) v1(8.53,77.74) v1(9.46,12.97) v1(9.89,14.95) v1(10.33,18.52) v1(10.29,17.85) v1(10.55,17.08) v1(10.85,49.52) v1(11.07,77.74) v1(11.11,31) v1(11.26,32.37) v1(12,12.97) v1(12.4,14.97) v1(13.61,77.74) v1(14.54,12.97) v1(14.94,76.06) v1(14.94,14.97) v1(16.15,77.74) v1(16.19,51.77) v1(16.34,63.41) v1(16.47,44.92) v1(16.47,32.42) v1(16.47,29.99) v1(16.57,73.78) v1(16.63,50.14) v1(16.62,47.87) v1(16.64,68.59) v1(16.69,66.64) v1(16.8,12.87) v1(16.95,64.68) v1(16.95,21.45) v1(17.25,76.01) v1(17.48,14.97) v1(17.58,63.44) v1(17.68,77.61) v1(17.73,22.81) v1(18.22,65.67) v1(18.24,67.5) v1(18.52,54.29) v1(18.91,53.43) v1(19.03,63.46) v1(18.95,12.33) v1(19.11,73.78) v1(19.54,66.44) v1(19.46,64.71) v1(19.56,21.53) v1(19.87,13.48) v1(19.95,15.03) v1(20.1,75.96) v1(20.15,62.09) v1(20.27,22.81) v1(20.53,55.08) v1(20.58,67.38) v1(20.73,65.6) v1(21.01,63.26) v1(21.01,11.32) v1(21.06,54.29) v1(21.23,77.74) v1(21.45,53.43) v1(21.65,73.78) v1(21.75,64.71) v1(21.9,21.5) v1(22.54,65.62) v1(22.49,15.03) v1(22.56,76.06) v1(22.61,56.55) v1(22.66,10.07) v1(22.84,13.32) v1(23.07,55.08) v1(23.25,11.52) v1(23.77,77.74) v1(24.09,8.47) v1(24.19,73.78) v1(24.16,56.48) v1(25,66.31) v1(25.03,15.03) v1(24.97,6.92) v1(25.1,76.06) v1(25.61,55.08) v1(25.61,5.3) v1(25.79,11.52) v1(25.91,9.97) v1(25.99,3.29) v1(26.04,67.63) v1(26.09,0.88) v1(26.31,77.74) v1(26.24,8.41) v1(26.53,53.43) v1(26.73,73.78) v1(26.7,56.48) v1(26.88,66.28) v1(27.18,5.07) v1(27.6,0.76) v1(27.64,76.06) v1(27.9,55.01) v1(27.95,67.58) v1(28.1,10.48) v1(28.33,11.52) v1(28.41,20.81) v1(28.53,3.29) v1(28.78,8.41) v1(28.85,77.74) v1(29.14,69.18) v1(29.09,66.28) v1(29.07,53.43) v1(29.27,73.78) v1(29.6,6.52) v1(30.05,67.65) v1(30.14,0.76) v1(30.18,76.06) v1(30.41,71.39) v1(30.44,55.01) v1(30.56,62.8) v1(30.95,20.81) v1(31.07,69.1) v1(31.07,3.29) v1(31.32,8.41) v1(31.39,77.74) v1(31.61,53.43) v1(31.6,14.31) v1(31.73,66.31) v1(31.81,73.78) v1(31.78,56.48) v1(31.98,70.07) v1(32.49,67.63) v1(32.47,6.47) v1(32.72,76.06) v1(32.68,0.76) v1(32.75,10.1) v1(32.98,55.01) v1(33.33,71.49) v1(33.41,6.03) v1(33.51,66.18) v1(33.64,69.1) v1(33.61,3.29) v1(33.93,77.74) v1(33.86,8.41) v1(34.07,17.97) v1(34.15,53.43) v1(34.32,56.48) v1(34.35,73.78) v1(34.4,19.75) v1(34.65,67.55) v1(34.75,57.75) v1(34.88,70.07) v1(35.03,16.07) v1(34.96,10.02) v1(35.22,0.76) v1(35.52,55.01) v1(35.46,12.49) v1(35.9,71.49) v1(36.15,3.29) v1(36.4,8.41) v1(36.47,77.74) v1(36.53,18.23) v1(36.61,16.22) v1(36.69,53.43) v1(36.84,19.83) v1(36.89,73.78) v1(36.86,56.48) v1(36.86,14.31) v1(37.37,22.81) v1(37.37,6.04) v1(37.62,21.43) v1(37.69,8.57) v1(37.76,0.76) v1(38,16.75) v1(38.06,55.01) v1(38.69,3.29) v1(38.89,71.64) v1(38.94,8.41) v1(39.11,67.57) v1(39.04,60.17) v1(39.07,18.23) v1(39.12,13.43) v1(39.19,65.11) v1(39.19,62.57) v1(39.23,53.43) v1(39.38,19.83) v1(39.58,14.75) v1(39.91,22.81) v1(40.16,21.43) v1(40.21,11.37) v1(40.3,0.76) v1(40.6,55.01) v1(41.13,6.03) v1(41.23,3.29) v1(41.48,8.41) v1(41.79,12.65) v1(41.79,10.11) v1(42.62,55.61) v1(42.7,21.43) v1(42.84,0.76) v1(43.54,8.45) v1(43.93,72.13) v1(43.85,12.47) v1(43.85,9.93) v1(44.79,20.31) v1(45.16,55.61) v1(45.38,0.76) v1(45.68,14.01) v1(45.83,21.11) v1(45.83,10.95) v1(45.83,8.41) v1(45.83,5.87) v1(45.83,3.33) v1(46.03,76.66) v1(46.03,74.12) v2(4.6,32.15)
3D3V_CARD: length 34.4
  TOP w0.762: v3(12.05,25.34) 11.46,25.34 10.22,26.58 6.86,26.58 v2(4.79,28.66) 4.31,29.13 4.31,30.68 v3(2.42,32.58)
  L3 w0.762: v3(1.59,43.69) 1.59,33.4 v3(2.42,32.58)
  BOTTOM w0.762: v3(12.05,25.34) 12.68,25.34 13.24,25.9 C314.1 C313.1 13.26,27.65 13.26,33.87
3D3V_CARD_S0: length 2.6
  TOP w0.305: CARD34.8 3.7,42.73 3.56,42.86 v1(3.44,42.86)
  vias: v1(7.67,45.28) v2(6.36,45.35)
3D3V_S0: length 7
  TOP w0.508: v1(2.67,42.23) 2.29,41.85 R318.1 ; R318.1 v2(1.33,41.4) ; R318.1 2.36,41.47 R313.1 ; R317.1 3.18,38.74 R316.1 v1(3.12,37.91)
  TOP w1.016: v3(2.55,47.44) 3.55,47.44 R322.1
  BOTTOM w1.016: v3(9.78,76.64) R512.1 9.78,75.48
  vias: v3(8.13,24.83) v3(8.13,23.69)
3D3V_S5: length 4.6
  BOTTOM w0.508: v2(21.88,66.46) 22.29,66.88 C509.1 ; R519.1 C509.1 ; C509.1 22.49,67.57 C507.1 21.37,68.33 Q503.S
3D3V_WLAN_S0:
  vias: v2(6.84,54.37) v3(4.83,51.75) v3(6.61,69.66)
12MHZ_IN: length 3.9
  TOP w0.127: R323.1 11.18,45.34 11.82,44.71 v2(11.82,44.69) 11.75,44.69 11.32,44.26 10.85,44.26 10.13,43.54 CARD34.24
+RTC_VCC: length 38
  TOP w0.508: v3(8.16,25.67) 6.56,25.67 AFTP2508.1
  L3 w0.508: v1(29.24,13.91) 26.85,16.3 8.29,16.3 8.03,16.55 8.02,16.55 6.1,18.47 6.1,25.08 6.69,25.67 v3(8.16,25.67)
  BOTTOM w0.305: IOBD2.17 8.51,26.09 8.16,25.74 v3(8.16,25.67)
  BOTTOM w0.508: v1(29.24,13.91) 29.85,13.3 R601.1
AUX_EN_WOWL: length 1.4
  TOP w0.102: AFTP6117.1 28.52,70.11 v1(27.97,70.11)
  BOTTOM w0.102: R516.1 v1(27.97,70.11)
AUX_EN_WOWL_R: length 2.7
  BOTTOM w0.102: Q504.G 25.85,71.05 v2(26.68,71.87) 27.18,71.36 R516.2
BLUETOOTH_EN: length 48.9
  TOP w0.102: R521.2 3.42,62.94 3.94,62.42 D503.K v1(3.94,60.64) ; v1(8.13,19.5) 8.77,18.86 AFTP6112.1
  L4 w0.102: v1(8.13,19.5) 8.13,19.52 8.95,20.33 8.95,29.29 4.1,34.14 4.1,43.14 3.94,43.29 v1(3.94,60.64)
  BOTTOM w0.102: v1(8.13,19.5) 8.23,19.59 IOBD2.4
BLUETOOTH_EN_R: length 7.8
  TOP w0.102: R521.1 5.31,63.08 v2(5.34,63.06) 6.37,63.06 R502.2 6.39,61.83 D503.A 5.47,61.66 v1(4.96,62.17)
  BOTTOM w0.102: WLAN1.54 5.39,63.52 5.21,63.35 5.21,62.42 v1(4.96,62.17)
CARD_AV18: length 2.6
  TOP w0.305: CARD34.1 9.28,44.57 9.66,44.95 v2(10.29,44.95) C318.1
CARD_RREF: length 3.1
  TOP w0.305: R326.1 9.35,46.81 v2(9.35,45.96) 9.35,45.35 8.78,44.78 CARD34.2
CLKREQ_PCIE#1: length 52.3
  TOP w0.102: AFTP6109.1 9.53,20.53 v1(10.04,21.04)
  L4 w0.102: v1(10.04,21.04) 10.04,21.08 10.46,21.5 10.46,21.86 10.04,22.28 10.04,28.86 9.53,29.37 9.53,48.44 9.81,48.72 9.81,58.01 16.24,64.43 v1(16.24,64.81)
  BOTTOM w0.102: WLAN1.53 14.76,63.27 15.31,63.81 15.44,63.81 16.24,64.61 v1(16.24,64.81) ; v1(10.04,21.04) 10.04,21.04 9.99,21.09 IOBD2.7
JIO3_PCIE_WAKE#: length 1.8
  TOP w0.102: R524.1 3.78,68.1 AFTP6115.1
JIO3_PCIE_WAKE#_R: length 3.7
  TOP w0.102: v1(5.09,67.88) 5.39,67.88 5.72,67.55 v2(5.72,67.45) 5.72,67.43 5.42,67.12 R524.2
  BOTTOM w0.102: v1(5.09,67.88) 5.45,67.52 WLAN1.70
KBC_PWRBTN#: length 4.3
  BOTTOM w0.102: IOBD2.6 10.55,20.59 v2(10.85,20.89) 11.21,20.54 11.21,19.43 EC611.1 R613.1
KBC_PWRBTN#_C: length 30
  TOP w0.102: AFTP716.1 14,17.44 v1(13.98,17.41)
  L3 w0.102: v1(36.68,11.24) 32.65,11.24 27.16,16.73 16.52,16.73 15.83,17.41 v1(13.98,17.41)
  BOTTOM w0.102: v1(13.98,17.41) ED609.1 12.97,17.41 12.05,18.34 R613.2 ; PWBD1.3 36.69,11.23 v1(36.68,11.24)
LOOP: length 33.1
  TOP w0.102: v2(10.62,19.52) 10.62,19.88 v1(10.39,20.11)
  L4 w0.102: v1(10.39,20.11) 10.55,20.11 10.8,20.36 10.8,21.88 10.34,22.34 10.34,24.26 11.08,25 11.08,29.02 12.12,30.06 12.12,37.35 11.79,37.68 11.79,43.93 v1(10.95,44.77)
  BOTTOM w0.102: IOBD2.1 9.65,18.09 9.84,18.28 9.84,18.84 10.39,19.39 v1(10.39,20.11) ; IOBD2.50 9.74,42.59 10.14,42.99 10.14,43.96 v1(10.95,44.77)
PCIE_RX_CPU_N5: length 31.6
  TOP w0.102: v2(17.99,61.48) 17.99,61.48 v1(17.99,60.89)
  L6 w0.127: v1(10.62,38.95) 10.52,39.05 9.63,39.05 9.26,39.42 9.26,44.24 11.49,46.47 11.49,58.15 13.99,60.66 17.76,60.66 v1(17.99,60.89)
  BOTTOM w0.102: IOBD2.43 10.48,39.09 v1(10.62,38.95) ; v1(17.99,60.89) 17.95,60.92 R522.2
PCIE_RX_CPU_P5: length 31.4
  TOP w0.102: v1(17.99,60.1) 18.31,60.1 v2(18.57,60.36)
  L6 w0.127: v1(10.62,39.73) 10.62,39.57 10.37,39.32 9.74,39.32 9.53,39.53 9.53,44.13 11.75,46.36 11.75,58.04 14.1,60.39 17.7,60.39 v1(17.99,60.1)
  BOTTOM w0.102: v1(17.99,60.1) 17.95,60.06 R523.2 ; v1(10.62,39.73) 10.62,39.56 10.39,39.32 9.8,39.32 9.53,39.59 IOBD2.44
PCIE_TX_WLAN_N5: length 29.1
  TOP w0.102: v1(10.62,38.29) 10.93,38.29 v2(11.16,38.52)
  L6 w0.127: v1(16.14,59.41) 15.78,59.06 14.9,59.06 13.01,57.17 13.01,41.82 11.96,40.76 11.96,38.61 11.39,38.04 10.97,38.04 10.72,38.29 v1(10.62,38.29)
  BOTTOM w0.102: v1(10.62,38.29) 10.42,38.09 IOBD2.41 ; v1(16.14,59.41) 15.86,59.13 15.14,59.13 15.01,59.27 WLAN1.37
PCIE_TX_WLAN_P5: length 29.2
  L6 w0.127: v1(16.14,58.62) 15.97,58.79 15.01,58.79 13.28,57.06 13.28,41.71 12.22,40.65 12.22,38.5 11.5,37.77 11.06,37.77 10.84,37.56 v1(10.67,37.56)
  BOTTOM w0.102: v1(10.67,37.56) 10.57,37.56 10.27,37.86 9.96,37.86 9.69,37.59 IOBD2.40 ; WLAN1.35 15.01,58.77 15.14,58.91 15.86,58.91 v1(16.14,58.62) 16.4,58.62 v2(16.64,58.87)
PEG_CLK1_CPU: length 38
  TOP w0.102: v2(10.67,36.72) 10.67,36.63 10.05,36.01 v1(10.04,36.01)
  L6 w0.127: v1(15.78,61.94) 16.35,62.51 17.82,62.51 19.07,61.27 19.07,58.76 14.1,53.79 14.1,40.39 13.34,39.63 13.34,37.13 12.34,36.13 10.17,36.13 v1(10.04,36.01)
  BOTTOM w0.102: v1(15.78,61.94) 15.73,61.89 15.04,61.89 14.92,61.77 WLAN1.47 ; IOBD2.37 9.96,36.09 v1(10.04,36.01)
PEG_CLK1_CPU#: length 37.1
  L6 w0.127: v1(16.49,61.89) 16.49,62.04 16.69,62.24 17.71,62.24 18.8,61.16 18.8,58.87 13.83,53.9 13.83,40.5 13.07,39.74 13.07,37.24 12.23,36.4 10.28,36.4 10.08,36.6 v1(10.08,36.64)
  BOTTOM w0.102: v1(16.49,61.89) 16.49,62.37 16.29,62.57 16.03,62.57 ; WLAN1.49 14.9,62.27 15.05,62.12 15.35,62.12 15.6,62.37 15.6,62.37 15.8,62.57 16.03,62.57 ; v1(10.08,36.64) 10.04,36.64 9.99,36.59 IOBD2.38 ; 16.03,62.57 v2(16.03,62.75)
PLT_RST#: length 48.2
  TOP w0.114: AFTP6108.1 8.54,21.68 v1(10.03,21.68)
  L4 w0.114: v1(5.09,61.41) 5.09,60.39 4.29,59.6 4.29,43.27 4.33,43.24 4.33,34.23 9.73,28.83 9.73,21.97 v1(10.03,21.68)
  BOTTOM w0.114: v1(10.03,21.68) 9.94,21.59 IOBD2.8 ; WLAN1.52 5.81,63.02 5.47,62.68 5.47,61.79 v1(5.09,61.41)
RTC_VCC_C: length 2.9
  BOTTOM w0.508: RTC1.1 29.89,12.13 R601.2 29.41,12.17 v2(28.91,12.66)
SD_CD#: length 20.2
  TOP w0.102: R3314.2 2.36,40.58 R318.2 1.72,39.94 1.72,37.09 v2(2.44,36.36) v1(3.05,35.75)
  L3 w0.102: v1(10.9,35.27) 10.67,35.27 10.22,34.81 9.91,34.81 9.14,34.05 6.28,34.05 4.58,35.75 v1(3.05,35.75)
  BOTTOM w0.102: v1(10.9,35.27) 11.02,35.38 11.02,36.91 12.07,37.96 R321.1 12.58,38.3 Q3302.2
SD_CD#_C: length 3.7
  BOTTOM w0.102: SD1.4 15.42,39.36 v2(14.03,37.96) R321.2
SD_CD#_CARD: length 25.2
  TOP w0.102: R313.2 4.04,41.47 v2(4.76,42.18) 5.21,41.72 CARD34.10 ; R313.2 R3314.1 ; R313.2 4.01,41.66 v1(3.44,42.23)
  L3 w0.102: v1(3.44,42.23) 3.44,39.74 4.48,38.7 4.93,38.7 5.03,38.8 5.03,39.77 5.13,39.87 5.33,39.87 5.43,39.77 5.43,38.8 5.53,38.7 5.74,38.7 5.84,38.8 5.84,39.77 5.94,39.87 6.14,39.87 6.25,39.77 6.25,38.8 6.35,38.7 6.55,38.7 6.65,38.8 6.65,39.77 6.75,39.87 6.96,39.87 7.06,39.77 7.06,38.8 7.16,38.7 7.61,38.7 9.77,40.85 10.55,40.85 10.87,40.53 11.74,40.53 12.12,40.15 v1(12.76,40.15)
  BOTTOM w0.102: v1(12.76,40.15) 13.23,40.62 Q3302.6
SD_MMC_CLK/MS_DATA2: length 30.5
  TOP w0.114: R324.1 8.62,36.93 C315.1 8.6,36.04 9.9,34.75 10.54,34.75 v1(10.67,34.61)
  L3 w0.114: v1(10.67,34.61) 12.59,32.7 12.59,31.65 12.47,31.54 11.88,31.54 11.77,31.42 11.77,31.19 11.88,31.08 12.47,31.08 12.59,30.96 12.59,30.74 12.47,30.62 11.39,30.62 11.26,30.49 11.26,30.3 11.39,30.16 12.47,30.16 12.59,30.05 12.59,24.71 v1(12.38,24.5)
  BOTTOM w0.114: SD1.7 16.16,33.75 14.05,31.64 v2(14.05,28.69) 14.05,25.38 EC311.1 13.2,24.58 13.11,24.5 v1(12.38,24.5)
SD_MMC_CMM/MS_DATA3: length 36.1
  TOP w0.114: v1(11.08,41.67) 10.63,41.22 CARD34.20
  L3 w0.114: v1(12.5,42.03) 14.08,42.03 14.23,42.18 14.23,47.65 14.14,47.74 13.2,47.74 13.09,47.85 13.09,48.08 13.2,48.2 14.14,48.2 14.26,48.31 14.26,48.54 14.14,48.65 13.2,48.65 13.09,48.77 13.09,49 13.2,49.11 14.14,49.11 14.26,49.23 14.26,49.45 14.14,49.57 13.2,49.57 13.09,49.68 13.09,49.91 13.2,50.03 14.14,50.03 14.26,50.14 14.26,50.51 14.41,50.66 14.59,50.66 14.74,50.51 14.74,41.44 14,40.71 12.2,40.71 11.93,40.98 11.93,40.98 11.23,41.67 v1(11.08,41.67)
  BOTTOM w0.114: v1(12.5,42.03) 12.97,42.5 EC313.1 13.14,42.5 v2(14.08,42.5) 15.05,42.5 SD1.3
SD_MMC_DAT1: length 34.1
  TOP w0.114: CARD34.12 5.45,40.24 v2(5.45,37.53) 3.05,35.13 v1(3.05,35.12)
  L3 w0.114: v1(11.64,22.87) 11.64,22.95 11.03,23.56 11.03,27.65 8.64,30.04 6.99,30.04 3.59,33.43 3.45,33.43 2.62,34.27 2.62,34.68 2.93,34.99 2.93,34.99 v1(3.05,35.12)
  BOTTOM w0.114: SD1.10 15.04,25.82 15.04,22.93 EC310.1 12.4,21.15 11.64,21.91 v1(11.64,22.87)
SD_MMC_DATA0/MS_DATA5: length 34
  TOP w0.114: v1(3.06,34.47) v2(4.6,36.01) 5.91,37.32 5.91,39 CARD34.13
  L3 w0.114: v1(3.06,34.47) 3.18,34.36 4.08,34.36 4.41,34.03 4.41,33.87 4.26,33.72 4.26,33.56 4.42,33.4 4.58,33.4 4.73,33.55 4.89,33.55 5.05,33.38 5.05,33.22 4.9,33.07 4.9,32.91 5.07,32.75 5.23,32.75 5.38,32.9 5.54,32.9 5.7,32.74 5.7,32.58 5.55,32.43 5.55,32.27 5.71,32.1 5.87,32.1 6.02,32.25 6.18,32.25 6.35,32.09 6.35,31.93 6.2,31.78 6.2,31.62 6.36,31.46 6.52,31.46 6.67,31.61 6.83,31.61 7.94,30.5 8.83,30.5 11.49,27.84 v1(11.49,23.81)
  BOTTOM w0.114: SD1.9 14.56,27.09 14.56,24.16 EC308.1 12.43,22.87 v1(11.49,23.81)
SD_MMC_DATA2/MS_BS: length 33.8
  TOP w0.114: CARD34.23 11.03,42.73 v1(11.04,42.71)
  L3 w0.114: v1(11.04,42.71) 10.55,42.71 10.37,42.54 10.37,41.5 10.24,41.37 10.05,41.37 9.91,41.5 9.91,44.86 9.8,44.97 9.57,44.97 9.46,44.86 9.46,41.19 9.32,41.06 9.13,41.06 9,41.19 9,43.71 8.89,43.83 6.84,43.83 6.73,43.71 6.73,42.27 6.62,42.15 6.39,42.15 6.27,42.27 6.27,43.71 6.16,43.83 6.03,43.83 5.9,43.96 5.9,44.15 6.03,44.29 8.89,44.29 9,44.4 9,44.86 8.89,44.97 8.36,44.97 8.21,45.12 8.21,45.45 8.36,45.6 v1(11.86,45.6)
  BOTTOM w0.114: SD1.1 14.17,46.35 14.03,46.22 v2(14.03,46.22) 13.79,45.98 EC312.1 12.24,45.98 v1(11.86,45.6)
SD_MMC_DATA3/MS_CLK: length 30.6
  TOP w0.114: v1(10.98,43.5) 11.06,43.58 11.53,43.58 R325.1
  L3 w0.114: v1(12.35,44.16) 12.99,44.16 13.14,44.31 13.14,46.01 12.99,46.17 8.85,46.17 8.69,46.32 8.69,46.55 8.85,46.7 11.54,46.7 11.66,46.83 11.66,49.77 11.82,49.93 12.38,49.93 12.53,49.77 12.53,47.41 12.68,47.26 13.62,47.26 13.77,47.11 13.77,42.86 13.49,42.58 11.89,42.58 v1(10.98,43.5)
  BOTTOM w0.114: v1(12.35,44.16) 12.39,44.2 EC314.1 v2(14.03,44.2) 14.47,43.76 SD1.2
SD_MMC_DATA3/MS_CLK_R: length 3.2
  TOP w0.114: CARD34.22 10.77,42.23 10.87,42.13 11.26,42.13 11.56,41.82 11.77,41.82 v2(11.92,41.98) 12.06,42.12 12.06,42.53 R325.2
SD_WP#/MS_DATA1: length 45.5
  TOP w0.102: v1(3.05,37.28) 3.03,37.28 v2(2.5,37.81) 2.23,38.08 R316.2 R314.2
  L3 w0.102: v1(10.95,22.75) 10.04,23.66 10.04,27.87 8.32,29.59 6.66,29.59 2.17,34.08 2.17,36.39 2.48,36.7 v1(3.05,37.28) 6.51,37.28 9.86,40.62 10.45,40.62 10.98,40.1 v1(11.33,40.1)
  BOTTOM w0.102: Q3302.5 12.58,40.77 12.21,40.4 12.2,40.4 11.89,40.1 v1(11.33,40.1) ; v1(10.95,22.75) 10.95,21.96 12.15,20.77 12.15,20.36 13.07,19.44 EC309.1 13.72,19.44 15.58,21.3 15.58,24.31 SD1.11
SD_WP#/MS_DATA1_C: length 20
  TOP w0.102: R317.2 4.71,40.39 4.71,40.83 5.1,41.22 CARD34.11 ; R317.2 3.88,39.69 R314.1 ; R317.2 4.01,39.63 4.4,39.23 4.4,37.86 v2(4.05,37.51) v1(3.05,36.51)
  L3 w0.102: v1(3.05,36.51) 8.79,36.51 10.04,35.27 v1(10.04,35.24)
  BOTTOM w0.102: Q3302.3 11.93,38.78 11.13,37.99 11.13,37.35 10.79,37.01 10.79,35.99 v1(10.04,35.24)
SDREG: length 2.8
  TOP w0.305: C319.1 6.78,37.82 v2(7.73,38.77) 8.28,39.33 CARD34.16
SP5: length 2.2
  TOP w0.114: R324.2 9.43,38.52 v2(9.18,38.77) 9.28,38.88 CARD34.18
USB20_VCCC: length 3.6
  TOP w0.305: v1(28.23,60.9) 28.15,60.82 AFTP3406.1
  BOTTOM w0.508: 33.46,61.2 33.46,62.6 33.25,62.8 U402.5
USB_CPU_PN2_C: length 41
  TOP w0.102: v2(25.74,62.8) 25.33,63.21 v1(25.08,63.21)
  L6 w0.127: v1(11.13,33.09) 10.96,33.25 10.96,33.58 11.21,33.82 13.47,35.5 14.38,37.58 14.76,38.88 14.88,40.34 14.88,51.44 19.84,58.51 19.84,59.29 21.95,62.37 24.35,63.38 24.47,63.38 24.68,63.19 v1(25.08,63.21)
  BOTTOM w0.102: IOBD2.32 9.58,33.59 9.65,33.52 10.69,33.52 v1(11.13,33.09) ; R4033.1 26.15,63.41 25.28,63.41 v1(25.08,63.21)
USB_CPU_PN5_C: length 23.2
  TOP w0.102: v1(6.87,49.98) 6.97,49.87 7.25,49.87 7.5,50.12 7.5,51.09 ; 7.5,51.09 7.5,51.4 7.73,51.63 8.25,51.63 R510.2 ; 7.5,51.09 v2(7.32,51.09)
  L6 w0.127: v1(6.87,49.98) 7.05,49.79 7.52,49.79 7.8,49.5 7.8,48.19 5.53,45.91 5.53,36.45 6.97,35 7.66,35 v1(7.93,35.27)
  BOTTOM w0.102: IOBD2.35 8.73,35.09 8.58,34.94 8.26,34.94 v1(7.93,35.27)
USB_CPU_PN7_C: length 27.4
  TOP w0.102: v1(5.19,48.68) 5.22,48.68 5.44,48.9 5.44,49.18 5.56,49.3 ; 5.56,49.3 5.65,49.39 6.2,49.39 6.74,48.86 6.82,48.78 7.77,48.78 8,48.54 8,47.73 R319.1 ; 5.56,49.3 v2(5.44,49.42)
  L6 w0.127: v1(8.06,32.23) 8.06,32.08 7.69,31.71 7.43,31.71 4.46,34.68 4.46,48.85 4.74,49.13 5.36,49.13 5.45,49.04 5.45,48.86 5.27,48.68 v1(5.19,48.68)
  BOTTOM w0.102: IOBD2.29 8.81,32.09 8.54,31.82 8.3,31.82 8.06,32.06 v1(8.06,32.23)
USB_CPU_PP2_C: length 40.7
  TOP w0.102: v1(25.05,63.87) 25.26,64.07 v2(25.63,64.07)
  L6 w0.127: v1(10.47,33.09) 10.47,33.11 10.7,33.34 10.7,33.68 11.05,34.04 13.25,35.67 14.13,37.67 14.5,38.93 14.61,40.35 14.61,51.53 19.58,58.59 19.58,59.38 21.78,62.59 24.29,63.64 24.34,63.64 24.46,63.65 24.65,63.85 v1(25.05,63.87)
  BOTTOM w0.102: v1(25.05,63.87) 25.27,63.64 26.11,63.64 R4032.1 ; IOBD2.31 9.51,33.09 9.71,33.29 10.17,33.29 10.37,33.09 10.47,33.09 v1(10.47,33.09)
USB_CPU_PP5_C: length 23.2
  TOP w0.102: 7.56,49.86 7.35,49.65 7.17,49.65 v1(6.87,49.34) ; 7.56,49.86 7.73,50.03 7.73,51.3 7.82,51.4 8.32,51.4 R511.2 ; 7.56,49.86 v2(7.68,49.75)
  L6 w0.127: v1(6.87,49.34) 6.87,49.35 7.04,49.52 7.41,49.52 7.54,49.39 7.54,48.3 5.26,46.02 5.26,36.34 6.86,34.74 7.68,34.74 v1(7.93,34.48)
  BOTTOM w0.102: v1(7.93,34.48) 8.16,34.71 8.62,34.71 8.74,34.59 IOBD2.34
USB_CPU_PP7_C: length 27.4
  TOP w0.102: 6.63,48.65 6.11,49.16 5.75,49.16 5.67,49.09 5.67,48.88 v1(5.92,48.63) ; 6.63,48.65 v2(6.51,48.53) ; 6.63,48.65 6.72,48.55 7.67,48.55 7.77,48.45 7.77,47.75 R320.1
  L6 w0.127: v1(5.92,48.63) 5.92,48.93 5.47,49.39 4.63,49.39 4.2,48.96 4.2,34.57 4.61,34.16 7.32,31.44 v1(8.06,31.44)
  BOTTOM w0.102: IOBD2.28 8.2,31.59 v1(8.06,31.44)
USB_DN7_R: length 3.1
  TOP w0.102: R319.2 8.02,46.29 8.02,45.87 8.06,45.82 8.33,45.55 8.33,45.12 ; 8.33,45.12 8.33,45 8.13,44.8 8.13,44.66 8.2,44.59 8.21,44.59 8.28,44.52 CARD34.3 ; 8.33,45.12 v2(8.46,45.12)
USB_DP7_R: length 2.9
  TOP w0.102: R320.2 7.79,46.25 7.79,45.78 7.9,45.66 8.11,45.46 8.11,45.1 7.9,44.9 7.9,44.64 7.78,44.52 CARD34.4
USB_OC1#: length 54
  TOP w0.102: v1(25.61,57.67) 25.81,57.88 26.14,57.88 v2(26.17,57.9)
  L4 w0.102: v1(25.61,57.67) 24.87,58.41 20.67,58.41 14.38,52.12 14.38,24.77 13.42,23.81 13.42,21.44 11.34,19.37 8.64,19.37 v1(8.13,18.86)
  BOTTOM w0.102: U401.3 25.71,57.77 v1(25.61,57.67) ; v1(8.13,18.86) 8.36,19.09 IOBD2.3
USB_PN2_R: length 11.4
  TOP w0.102: v1(28.59,63.18) 28.26,62.85 AFTP3404.1
  BOTTOM w0.102: USB4.2 36.58,63.74 32.18,63.74 U402.4 31.43,63.76 31.2,63.53 30.3,63.53 30.05,63.29 28.69,63.29 v1(28.59,63.18) 27.36,63.18 R4033.2
USB_PN5_R: length 17.5
  TOP w0.102: R510.1 9.55,51.87 10.81,51.87 11.19,51.49 11.66,51.02 11.66,50.48 ; 11.66,50.48 AFTP6111.1 ; 11.66,50.48 11.66,47.74 11.42,47.5 10.74,47.5 v1(10.7,47.46)
  BOTTOM w0.102: v1(10.7,47.46) 11.69,47.46 12.22,48 15.62,48 16.11,48.48 16.11,50.89 15.73,51.27 WLAN1.5
USB_PP2_R: length 11.9
  TOP w0.102: AFTP3405.1 28.28,64.63 v1(28.28,63.76)
  BOTTOM w0.102: R4032.2 27.4,63.87 27.72,63.87 27.83,63.76 v1(28.28,63.76) U402.3 31.11,63.76 31.58,64.23 32.75,64.23 33,63.97 36.55,63.97 USB4.3
USB_PP5_R: length 17.2
  TOP w0.102: 11.44,48.58 11.44,50.92 11.03,51.33 10.71,51.64 10.27,51.64 10.22,51.59 10.22,51.22 10.14,51.14 R511.1 ; 11.44,48.58 11.44,47.84 11.33,47.73 11.04,47.73 10.7,48.07 v1(10.7,48.31) ; 11.44,48.58 AFTP6114.1
  BOTTOM w0.102: WLAN1.3 14.82,50.77 15.09,51.04 15.64,51.04 15.88,50.8 15.88,48.58 15.53,48.22 12.13,48.22 11.6,47.69 11.09,47.69 10.7,48.08 v1(10.7,48.31)
USB_PWR_EN#: length 51.7
  TOP w0.102: v1(23.02,57.67) 23.04,57.7 v2(23.04,58.46)
  L4 w0.102: v1(8.13,18.23) 8.86,18.95 11.25,18.95 13.65,21.35 13.65,23.71 14.61,24.68 14.61,52.03 20.56,57.98 22.71,57.98 v1(23.02,57.67)
  BOTTOM w0.102: v1(8.13,18.23) 8.5,18.59 IOBD2.2 ; U401.4 23.42,58.08 v1(23.02,57.67)
VOL_DOWN#: length 28.7
  TOP w0.102: AFTP718.1 7.63,22.16 v1(8.01,22.16)
  L3 w0.102: v1(8.01,22.16) 8.16,22.32 12.35,22.32 12.38,22.35 12.74,22.35 12.77,22.32 14.97,22.32 17.02,20.26 28.91,20.26 v1(29.67,19.5)
  BOTTOM w0.102: v1(29.67,19.5) 30.31,20.13 31.22,20.13 31.49,19.86 EC609.2 R614.1 ; v1(8.01,22.16) 8.08,22.09 IOBD2.9
VOL_DOWN#_R: length 14.7
  BOTTOM w0.102: v2(33.43,20.54) 33.43,19.84 R614.2 32.73,19.14 32.73,18.58 ED611.1 34.96,18.58 38.69,14.85 PWBD1.1
VOL_UP#: length 26.5
  TOP w0.102: AFTP717.1 11.69,20.45 11.68,20.46 v1(11.66,20.46)
  L3 w0.102: v1(11.66,20.46) 12.88,19.24 23.7,19.24 25.96,16.98 v1(30.13,16.98)
  BOTTOM w0.102: R615.1 EC610.2 30.17,16.94 v1(30.13,16.98) ; v1(11.66,20.46) 11.66,20.72 9.79,22.59 IOBD2.10
VOL_UP#_R: length 13.4
  BOTTOM w0.102: PWBD1.2 37.69,14.45 34.63,17.51 33.02,17.51 ED610.1 31.95,16.44 R615.2 31.48,15.72 v2(31.48,15.23)
WIFI_RF_EN: length 51.1
  TOP w0.102: v1(3.94,63.79) D504.K 3.94,66.07 R520.2 ; AFTP6110.1 7.37,19.37 v1(8.13,20.13)
  L4 w0.102: v1(3.94,63.79) 3.94,61.41 3.51,60.97 3.51,43.4 3.87,43.04 3.87,34.04 8.72,29.19 8.72,20.72 v1(8.13,20.13)
  BOTTOM w0.102: v1(8.13,20.13) 8.64,20.13 8.68,20.09 IOBD2.5
WIFI_RF_EN_R: length 6.7
  TOP w0.102: R520.1 v2(5.64,66.23) R501.2 6.55,65.03 D504.A v1(4.96,64.71)
  BOTTOM w0.102: v1(4.96,64.71) 5.65,64.02 WLAN1.56
WLAN_EN#: length 5.5
  BOTTOM w0.102: v2(23.42,66.46) 23.45,66.46 24.07,67.08 R519.2 24.07,69.53 Q504.D 22.61,70.99 R517.1
WLAN_EN_R#: length 4.5
  BOTTOM w0.102: C507.2 R517.2 21.56,70.11 Q503.G 21.02,70.66 22.23,71.87 v2(22.23,72.05)
WLANPWR: length 10.2
  BOTTOM w0.508: R514.1 15.32,71.95 v2(17.63,71.95) C508.1 19.88,70.42 Q503.D
WLANTX_N3: length 2.5
  BOTTOM w0.102: WLAN1.43 15.2,60.77 15.22,60.75 16.28,60.75 R522.1
WLANTX_P3: length 2.8
  BOTTOM w0.102: R523.1 16.08,60.06 15.93,60.21 15.93,60.4 15.82,60.52 15.29,60.52 15.04,60.27 WLAN1.41

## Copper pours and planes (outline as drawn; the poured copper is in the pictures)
5V_S5 on TOP: 11.69,25.97 10.55,27.12 7.65,27.12 7.5,27.27 7.5,30.11 9.18,31.79 11.44,31.79 11.64,31.99 11.64,41.21 12.02,41.59 12.05,41.59 12.33,41.87 12.33,53.15 12.34,53.16 12.34,53.65 21.88,63.18 24.64,63.18 25.03,62.8 25.03,60.77 24.39,60.14 23.25,60.14 15.61,52.5 15.61,32.64 15.25,32.27 15.25,26.99 14.23,25.97
5V_S5 on BOTTOM: 7.75,26.99 7.5,27.24 7.5,28.89 7.88,29.28 9.53,29.28 9.53,26.99
5V_S5 on BOTTOM: 22.97,59.96 22.46,60.47 22.46,62.02 23.25,62.8 24.52,62.8 24.9,62.42 24.9,61 24.72,60.82 24.72,60.14 24.54,59.96 ; 2 cut-outs
GND on TOP: outline of 148 points within 0.51,0.51 49.14,77.99
GND on BOTTOM: 11.28,48.55 10.5,49.34 10.5,49.87 11.06,50.43 15.4,50.43 15.58,50.26 15.58,48.96 15.17,48.55
GND on BOTTOM: outline of 211 points within 0.51,0.51 49.14,77.99 ; 12 cut-outs
GND on BOTTOM: 28.91,62.5 28.91,63.03 29.01,63.13 30.79,63.13 30.82,63.11 30.82,62.68 30.64,62.5
GND on L2GND, L5VCC, L7GND: 26.27,0.51 25.92,0.65 25.78,1 25.78,2.21 22.7,9.64 15.27,12.72 3.62,12.72 3.38,12.78 3.21,12.95 1.2,17.42 0.51,22.28 0.51,77.5 0.65,77.85 1,77.99 45.79,77.99 46.14,77.85 46.28,77.5 46.28,73.87 46.72,72.8 47.79,72.36 49.14,72.36 49.14,71.38 48.94,71.18 46.53,71.18 46.16,71.69 45.57,71.88 41.32,71.88 40.19,72.34 39.44,71.37 39.44,69.83 35.95,69.83 34.95,68.83 35.95,67.82 39.44,67.82 39.44,59.92 35.95,59.92 34.95,58.92 35.95,57.91 39.44,57.91 39.44,56.37 40.19,55.4 41.32,55.86 45.57,55.86 46.16,56.05 46.53,56.56 48.94,56.56 49.14,56.36 49.14,55.38 47.79,55.38 46.72,54.94 46.28,53.87 46.28,53.18 17.39,53.18 16.42,52.43 16.88,51.3 16.88,24.94 16.42,23.81 17.39,23.06 24.88,23.06 24.88,22.07 25.18,21.36 25.89,21.06 35.29,21.06 36,21.36 36.3,22.07 36.3,23.06 46.08,23.06 46.08,1 45.94,0.65 45.59,0.51
GND on L3: outline of 118 points within 0.51,0.51 49.14,77.99 ; 3 cut-outs
GND on L4: outline of 98 points within 0.51,0.51 49.14,77.99 ; 2 cut-outs
GND on L6: outline of 109 points within 0.51,0.51 49.14,77.99 ; 2 cut-outs
3D3V_CARD on TOP: 4.2,43.12 4.07,43.25 1.4,43.25 1.28,43.37 1.28,43.88 1.53,44.13 5.59,44.13 6.36,43.37 6.36,43.12
3D3V_CARD on BOTTOM: 13.01,33.69 12.78,33.92 12.78,36.84 13.04,37.1 15.3,37.1 16.47,35.93 16.72,35.93 16.88,35.77 16.88,34.82 16.64,34.58 14.76,34.58 13.87,33.69 ; 3 cut-outs
3D3V_CARD_S0 on TOP: 7.12,43.5 6.99,43.63 6.61,43.63 4.71,45.53 4.2,45.53 4.07,45.66 3.31,45.66 3.18,45.79 3.18,46.55 6.48,46.55 6.61,46.42 6.61,45.91 6.99,45.53 7.75,45.53 7.88,45.4 7.88,45.28 7.37,44.77 7.37,43.5 ; 2 cut-outs
3D3V_CARD_S0 on L3: 3.33,42.48 3.59,42.48 6,44.9 7.8,44.9 8.06,45.15 8.06,45.4 7.8,45.66 5.7,45.66 3.05,43.02 3.05,42.76
3D3V_S0 on BOTTOM: 7.88,23.43 7.75,23.56 7.75,24.96 8.01,25.21 9.53,25.21 9.53,23.43
3D3V_S0 on L6: 1.4,69.03 1.4,25.21 3.82,22.8 8.52,22.8 8.64,22.93 8.64,24.96 8.39,25.21 4.45,25.21 3.69,25.97 3.69,41.09 3.18,41.59 3.18,68.39 10.29,75.5 10.29,76.77 10.04,77.03 9.4,77.03
3D3V_WLAN_S0 on TOP: 4.45,51.37 4.32,51.5 4.32,53.53 6.99,56.2 6.99,67.12 5.85,68.26 5.85,69.66 6.48,70.3 7.25,70.3 8.13,69.41 8.13,55.31 5.98,53.15 5.98,51.75 5.59,51.37 ; 2 cut-outs
3D3V_WLAN_S0 on BOTTOM: 5.85,67.88 5.72,68.01 5.72,69.15 6.1,69.53 6.1,73.98 6.48,74.36 10.42,74.36 10.93,74.87 11.94,74.87 11.94,73.34 11.69,73.09 10.67,73.09 7.25,69.66 7.25,67.88 ; 1 cut-out
3D3V_WLAN_S0 on BOTTOM: 4.58,50.36 4.2,50.74 4.2,52.14 4.32,52.26 5.09,52.26 5.34,52.01 5.34,51.37 5.59,51.12 7.12,51.12 7.25,50.99 7.25,50.36
USB20_VCCC on BOTTOM: 27.13,58.97 26.88,59.22 26.88,59.5 26.45,59.93 25,59.93 24.95,59.98 24.95,60.52 25.03,60.59 25.03,61.43 25.08,61.48 26.24,61.48 26.82,62.05 28.21,62.05 28.81,61.46 33.48,61.46 34.32,62.3 36.58,62.3 36.96,61.91 37.85,61.91 38.23,61.53 38.23,60.26 37.98,60.01 35.16,60.01 34.12,58.97 ; 5 cut-outs

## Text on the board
Ref Des/Assembly Bottom: SD1
Ref Des/Silkscreen Bottom: M2L3 | M2L3.5 Only 13" ROR
Ref Des/Silkscreen Top: Slit | 15915-SC | Starlord13 R I/O | 448.07R01.00SC | MADE IN TAIWAN
